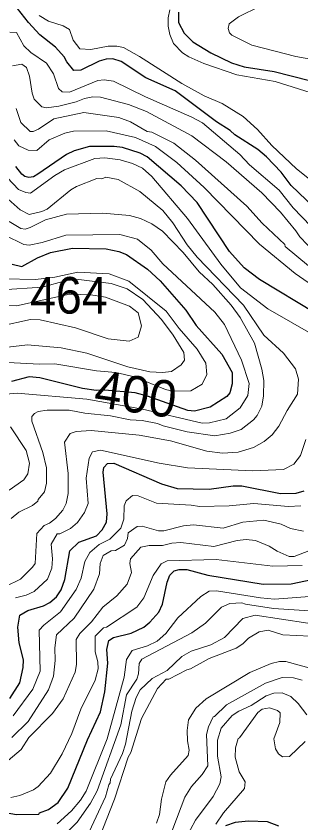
# Model space of a CAD drawing. Extents: x 673.3 to 698.5, y 6984.3 to 7012.3.
# Drawn here: x 677.867 to 678.489, y 6988.991 to 6990.755 of the extents above; entities that cross this region are included whole.
import ezdxf
from ezdxf.enums import TextEntityAlignment as Align

# ---------------------------------------------------------------- set-up
doc = ezdxf.new("R2010")
doc.units = 0
doc.header["$LTSCALE"] = 0.032
doc.layers.add('1', color=7, linetype='Continuous', lineweight=25)
doc.layers.add('2', color=7, linetype='Continuous', lineweight=13)
doc.layers.add('21', color=7, linetype='Continuous')
doc.layers.add('61', color=7, linetype='Continuous')

msp = doc.modelspace()

# ---------------------------------------------------------------- linework, layer by layer
at = {"layer": '1'}
for points in [[(678.5348, 6990.3208), (678.4679, 6990.3843), (678.446, 6990.4136), (678.4146, 6990.4474), (678.3951, 6990.4629), (678.3454, 6990.4954), (678.335, 6990.505), (678.3047, 6990.524), (678.2145, 6990.5913), (678.1504, 6990.6201), (678.0964, 6990.6557), (678.0785, 6990.6614), (678.0638, 6990.6606), (678.0483, 6990.6563), (678.0083, 6990.6365), (677.9931, 6990.6355), (677.9779, 6990.6545), (677.9723, 6990.6658), (677.9533, 6990.6872), (677.9191, 6990.7141), (677.8939, 6990.741), (677.8698, 6990.7716)], [(678.2222, 6990.7631), (678.2219, 6990.7407), (678.2341, 6990.7177), (678.2533, 6990.6987), (678.2923, 6990.6748), (678.3378, 6990.6523), (678.3656, 6990.6438), (678.431, 6990.6336), (678.5082, 6990.6142), (678.5381, 6990.6043), (678.5847, 6990.5818), (678.6337, 6990.5467), (678.7058, 6990.4795), (678.7374, 6990.4595), (678.7677, 6990.4588), (678.7872, 6990.4689), (678.8191, 6990.5), (678.8523, 6990.564), (678.8788, 6990.5944)], [(678.5218, 6990.1049), (678.3988, 6990.1789), (678.3654, 6990.2043), (678.3336, 6990.2401), (678.2629, 6990.3476), (678.2281, 6990.384), (678.1537, 6990.447), (678.1382, 6990.4553), (678.0994, 6990.4673), (678.0815, 6990.4699), (678.0273, 6990.4695), (677.9941, 6990.4603), (677.9768, 6990.4526), (677.9146, 6990.4094), (677.9046, 6990.4033), (677.8944, 6990.4018), (677.886, 6990.4044), (677.8791, 6990.409), (677.8662, 6990.4258)], [(677.8584, 6990.2128), (677.8797, 6990.2071), (677.9138, 6990.2264), (677.9419, 6990.2377), (677.9902, 6990.2477), (678.0641, 6990.246), (678.0912, 6990.2401), (678.1085, 6990.2334), (678.154, 6990.2014), (678.1821, 6990.1758), (678.2379, 6990.112), (678.2607, 6990.0785), (678.3163, 6990.0156), (678.3392, 6989.9759), (678.339, 6989.9506), (678.3342, 6989.9312), (678.3275, 6989.9235), (678.2908, 6989.9002), (678.257, 6989.8911), (678.2421, 6989.8929), (678.154, 6989.9243), (678.1275, 6989.9311), (678.0611, 6989.9374), (678.042, 6989.9367), (678.0124, 6989.9405), (677.9186, 6989.9644), (677.8956, 6989.9659), (677.8567, 6989.9561)], [(678.0548, 6989.632), (678.0648, 6989.6487), (678.0663, 6989.6665), (678.0573, 6989.7579), (678.0585, 6989.7677), (678.0664, 6989.7768), (678.0804, 6989.7777), (678.1847, 6989.7321), (678.2189, 6989.7224), (678.2889, 6989.7209), (678.3411, 6989.728), (678.3606, 6989.7281), (678.4447, 6989.7111), (678.4789, 6989.7118), (678.4964, 6989.7173)], [(677.853, 6989.2634), (677.8748, 6989.2971), (677.8822, 6989.3307), (677.883, 6989.3473), (677.8733, 6989.3847), (677.8709, 6989.4193), (677.8749, 6989.4452), (677.8926, 6989.4552), (677.9266, 6989.4657), (677.9406, 6989.4731), (677.9549, 6989.4857), (677.9653, 6989.501), (677.9735, 6989.5232), (677.9846, 6989.5856), (678.0037, 6989.605), (678.0429, 6989.6185), (678.0548, 6989.632)], [(677.7921, 6989.0228), (677.8681, 6989.0099), (677.9165, 6989.0105), (677.9184, 6989.0132), (677.9378, 6989.0202), (677.959, 6989.0361), (677.9801, 6989.0671), (678.0232, 6989.173), (678.0515, 6989.2343), (678.0606, 6989.2779), (678.0671, 6989.3402), (678.0656, 6989.3701), (678.0695, 6989.3898), (678.0799, 6989.3967), (678.1183, 6989.4059), (678.1463, 6989.4192), (678.1596, 6989.4297), (678.1791, 6989.4515), (678.1869, 6989.4695), (678.1969, 6989.5171), (678.2033, 6989.5325), (678.2127, 6989.5422), (678.2235, 6989.5449), (678.24, 6989.5449), (678.2861, 6989.5325), (678.4069, 6989.5132), (678.4681, 6989.514), (678.5137, 6989.523)], [(678.4412, 6988.9837), (678.4168, 6988.9935), (678.3746, 6988.9953), (678.3459, 6988.992), (678.3247, 6988.9847)]]:
    msp.add_lwpolyline(points, dxfattribs=at)
at = {"layer": '2'}
for points in [[(677.0774, 6990.8085), (677.118, 6990.7392), (677.1463, 6990.7225), (677.2022, 6990.698), (677.231, 6990.6757), (677.2435, 6990.6615), (677.256, 6990.6234), (677.2821, 6990.52), (677.2887, 6990.51), (677.3022, 6990.499), (677.384, 6990.4638), (677.5055, 6990.4177), (677.5778, 6990.3813), (677.5937, 6990.3661), (677.6099, 6990.3358), (677.6245, 6990.2827), (677.631, 6990.277), (677.6589, 6990.2211), (677.6967, 6990.2059), (677.7199, 6990.2013), (677.7579, 6990.1996), (677.8402, 6990.1808), (677.9096, 6990.1788)], [(678.4007, 6990.7768), (678.3532, 6990.7531), (678.3328, 6990.7382), (678.3303, 6990.7276), (678.3332, 6990.7183), (678.3384, 6990.7129), (678.382, 6990.6913), (678.4785, 6990.6668), (678.5313, 6990.6573)], [(678.5234, 6990.5833), (678.4331, 6990.6119), (678.3492, 6990.6263), (678.2775, 6990.6508), (678.2444, 6990.6656), (678.2309, 6990.6746), (678.2108, 6990.6952), (678.2028, 6990.7147), (678.1991, 6990.7329), (678.199, 6990.7509), (678.2031, 6990.7687)], [(677.9173, 6990.7559), (677.9381, 6990.7438), (677.9697, 6990.7337), (677.9838, 6990.7258), (677.9914, 6990.7022), (678.0062, 6990.6835), (678.0303, 6990.6816), (678.0681, 6990.6892), (678.0869, 6990.6891), (678.1016, 6990.6859), (678.1366, 6990.6666), (678.2293, 6990.6073), (678.2778, 6990.5805), (678.3174, 6990.5639), (678.3633, 6990.5353), (678.3947, 6990.5072), (678.4259, 6990.4721), (678.4802, 6990.4209), (678.508, 6990.398), (678.572, 6990.3302), (678.6114, 6990.2776), (678.6725, 6990.2221), (678.7436, 6990.1797)], [(678.5692, 6990.2348), (678.4723, 6990.3359), (678.4422, 6990.3742), (678.3774, 6990.4293), (678.3557, 6990.4526), (678.2746, 6990.5215), (678.2514, 6990.5342), (678.1497, 6990.5786), (678.0799, 6990.6126), (678.0596, 6990.6157), (678.0458, 6990.6143), (677.9835, 6990.5885), (677.9677, 6990.5891), (677.9596, 6990.5965), (677.949, 6990.6288), (677.9335, 6990.6516), (677.8993, 6990.6754), (677.8841, 6990.6897), (677.8681, 6990.7192), (677.8532, 6990.7193)], [(677.859, 6990.6459), (677.8796, 6990.65), (677.8897, 6990.6421), (677.8961, 6990.6237), (677.902, 6990.5865), (677.9065, 6990.5732), (677.9232, 6990.5563), (677.9335, 6990.5539), (677.9603, 6990.5578), (677.9981, 6990.5676), (678.0164, 6990.575), (678.0343, 6990.5783), (678.0514, 6990.5774), (678.1125, 6990.5613), (678.1521, 6990.5464), (678.2514, 6990.4927), (678.3259, 6990.436), (678.4043, 6990.3682), (678.4447, 6990.326), (678.4785, 6990.2857), (678.4868, 6990.2725), (678.5207, 6990.2371)], [(678.5873, 6990.142), (678.455, 6990.251), (678.4545, 6990.2552), (678.405, 6990.3022), (678.3711, 6990.3394), (678.2589, 6990.4395), (678.2116, 6990.4768), (678.1639, 6990.5007), (678.1535, 6990.5026), (678.1167, 6990.5237), (678.0913, 6990.5328), (678.015, 6990.5441), (677.9492, 6990.5299), (677.9159, 6990.5076), (677.9043, 6990.5026), (677.8977, 6990.5027), (677.8771, 6990.5225), (677.8669, 6990.5526)], [(677.863, 6990.4842), (677.8731, 6990.471), (677.8933, 6990.4618), (677.9121, 6990.461), (677.9393, 6990.4843), (677.9736, 6990.4989), (677.9922, 6990.5034), (678.0641, 6990.5042), (678.128, 6990.4893), (678.1716, 6990.4699), (678.2185, 6990.435), (678.2783, 6990.3802), (678.3993, 6990.2559), (678.4768, 6990.1924), (678.5148, 6990.1656)], [(678.5262, 6990.0521), (678.4173, 6990.1149), (678.3573, 6990.1611), (678.3144, 6990.2122), (678.2415, 6990.3121), (678.1634, 6990.4038), (678.1434, 6990.4221), (678.1217, 6990.4327), (678.0943, 6990.4405), (678.0612, 6990.4447), (678.0388, 6990.4438), (677.9729, 6990.4189), (677.9515, 6990.4062), (677.8987, 6990.3675), (677.8882, 6990.369), (677.8723, 6990.3758), (677.848, 6990.4016)], [(678.2409, 6990.2546), (678.2098, 6990.3029), (678.1879, 6990.3296), (678.1377, 6990.3716), (678.0897, 6990.3976), (678.0628, 6990.4025), (678.0541, 6990.3992), (678.0431, 6990.3995), (677.9993, 6990.3823), (677.9863, 6990.3748), (677.935, 6990.3331), (677.9232, 6990.3274), (677.8956, 6990.321), (677.8759, 6990.3314), (677.8368, 6990.366)], [(678.1166, 6989.8725), (678.1426, 6989.8705), (678.176, 6989.8642), (678.1882, 6989.8591), (678.2409, 6989.8461), (678.301, 6989.8373), (678.3352, 6989.8428), (678.3589, 6989.8513), (678.3861, 6989.872), (678.394, 6989.8818), (678.4042, 6989.9024), (678.4075, 6989.925), (678.4083, 6989.9583), (678.4041, 6989.9828), (678.3878, 6990.0395), (678.3564, 6990.096), (678.3371, 6990.1228), (678.2968, 6990.1678), (678.2671, 6990.1954), (678.2318, 6990.2377), (678.1866, 6990.2845), (678.1638, 6990.3008), (678.1386, 6990.3121), (678.1149, 6990.3187), (678.0564, 6990.3243), (677.9769, 6990.3217), (677.9313, 6990.3093), (677.898, 6990.2925), (677.8866, 6990.2893), (677.8773, 6990.2906), (677.8515, 6990.3058)], [(678.0212, 6989.9171), (678.1429, 6989.8957), (678.2733, 6989.865), (678.29, 6989.8654), (678.3258, 6989.8746), (678.3566, 6989.8986), (678.3733, 6989.9253), (678.3764, 6989.952), (678.3597, 6990.0028), (678.3224, 6990.081), (678.3011, 6990.1074), (678.1879, 6990.2133), (678.1622, 6990.243), (678.1325, 6990.267), (678.0936, 6990.2777), (677.9759, 6990.2761), (677.9242, 6990.26), (677.8958, 6990.2543), (677.8841, 6990.2553), (677.8423, 6990.2761)], [(677.8439, 6989.5082), (677.8763, 6989.5241), (677.903, 6989.5501), (677.9083, 6989.5582), (677.9125, 6989.6238), (677.9281, 6989.6413), (677.9397, 6989.6466), (677.9527, 6989.6569), (677.9691, 6989.675), (677.9767, 6989.689), (677.9807, 6989.7112), (677.9808, 6989.7548), (677.9727, 6989.8233), (677.9848, 6989.8427), (677.9984, 6989.8471), (678.0308, 6989.8486), (678.1358, 6989.8388), (678.2045, 6989.8265), (678.2835, 6989.8039), (678.3179, 6989.7997), (678.3527, 6989.8015), (678.3857, 6989.8117), (678.4089, 6989.8246), (678.4266, 6989.8393), (678.4416, 6989.8582), (678.4595, 6989.8924), (678.4824, 6989.928), (678.484, 6989.9613), (678.4775, 6989.9838), (678.4516, 6990.0178), (678.4088, 6990.0571), (678.3639, 6990.1228), (678.2626, 6990.2281), (678.2409, 6990.2546)], [(677.9096, 6990.1788), (677.9518, 6990.1842), (678.0017, 6990.1948), (678.0701, 6990.1916), (678.1137, 6990.1755), (678.1949, 6990.11), (678.2234, 6990.0721), (678.2625, 6990.0269), (678.2818, 6989.9964), (678.2837, 6989.9712), (678.2737, 6989.9503), (678.2492, 6989.9357), (678.2095, 6989.9347), (678.1932, 6989.9387), (678.1261, 6989.9659), (678.0849, 6989.9757), (678.0425, 6989.9794), (677.9515, 6989.9944), (677.9182, 6989.9937), (677.8485, 6989.9976)], [(677.8365, 6990.0295), (677.8921, 6990.0359), (677.9654, 6990.0295), (678.0212, 6990.0181), (678.111, 6989.9883), (678.1594, 6989.977), (678.1871, 6989.9757), (678.2065, 6989.978), (678.2278, 6989.9924), (678.2348, 6990.003), (678.2334, 6990.0197), (678.2102, 6990.0574), (678.1849, 6990.0916), (678.1442, 6990.1355), (678.1097, 6990.1588), (678.0749, 6990.1704), (678.0041, 6990.1793), (677.9772, 6990.1768), (677.9242, 6990.1622), (677.8355, 6990.1565)], [(677.8204, 6990.1229), (677.8679, 6990.1215), (677.984, 6990.1467), (678.0302, 6990.1458), (678.0625, 6990.1402), (678.1146, 6990.1205), (678.1341, 6990.1058), (678.1412, 6990.0777), (678.1339, 6990.0533), (678.1143, 6990.0442), (678.0685, 6990.049), (677.9966, 6990.0736), (677.9192, 6990.0912), (677.8986, 6990.0918), (677.8319, 6990.0767)], [(677.8372, 6989.9278), (677.8692, 6989.9302), (678.0212, 6989.9171)], [(677.8559, 6989.6567), (677.8731, 6989.6701), (677.9026, 6989.6848), (677.9146, 6989.6946), (677.9151, 6989.6982), (677.9287, 6989.7148), (677.9336, 6989.7341), (677.9335, 6989.7675), (677.9255, 6989.8012), (677.901, 6989.8696), (677.901, 6989.8793), (677.9072, 6989.8864), (677.9151, 6989.8902), (677.9347, 6989.8934), (677.983, 6989.8934), (678.0169, 6989.8869), (678.0736, 6989.8812), (678.1166, 6989.8725)], [(677.8515, 6989.7183), (677.8837, 6989.7411), (677.8928, 6989.7543), (677.896, 6989.7775), (677.8886, 6989.805), (677.8545, 6989.8568)], [(677.8657, 6989.4828), (677.8889, 6989.489), (677.9062, 6989.4973), (677.9354, 6989.524), (677.9449, 6989.5477), (677.9465, 6989.5685), (677.9433, 6989.6006), (677.957, 6989.6228), (677.9628, 6989.6231), (677.9861, 6989.6348), (678.0009, 6989.6481), (678.0166, 6989.6695), (678.0247, 6989.6894), (678.0199, 6989.745), (678.0265, 6989.7885), (678.0338, 6989.8021), (678.0513, 6989.8057), (678.1793, 6989.7778), (678.2413, 6989.7674), (678.3841, 6989.7607), (678.4518, 6989.764), (678.4743, 6989.7754), (678.4883, 6989.7944), (678.5003, 6989.8291)], [(678.4896, 6989.684), (678.4623, 6989.6826), (678.3864, 6989.6891), (678.3329, 6989.6842), (678.2681, 6989.6826), (678.2495, 6989.6857), (678.174, 6989.6899), (678.1339, 6989.7061), (678.1212, 6989.7069), (678.1077, 6989.6952), (678.103, 6989.6841), (678.1022, 6989.6551), (678.0955, 6989.6352), (678.0717, 6989.6115), (678.0483, 6989.5994), (678.0282, 6989.5825), (678.0169, 6989.5626), (678.0092, 6989.5261)], [(677.9522, 6989.3459), (677.9516, 6989.3735), (677.9555, 6989.4021), (677.994, 6989.4385), (678.0369, 6989.5018), (678.0491, 6989.5353), (678.0507, 6989.5581), (678.0574, 6989.5758), (678.0746, 6989.5861), (678.0842, 6989.5865), (678.104, 6989.5982), (678.1102, 6989.6126), (678.1119, 6989.6252), (678.1317, 6989.639), (678.1426, 6989.6401), (678.1779, 6989.6296), (678.1896, 6989.6296), (678.2326, 6989.6409), (678.2549, 6989.6426), (678.3199, 6989.6353), (678.3629, 6989.6482), (678.4088, 6989.6532), (678.4466, 6989.6442), (678.4668, 6989.6346), (678.4949, 6989.6288)], [(678.5558, 6989.6051), (678.4746, 6989.5735), (678.464, 6989.5737), (678.4374, 6989.5853), (678.42, 6989.5961), (678.3902, 6989.6082), (678.37, 6989.6108), (678.3503, 6989.6084), (678.2994, 6989.5954), (678.2271, 6989.6044), (678.2075, 6989.6028), (678.1866, 6989.5977), (678.1581, 6989.5978), (678.1394, 6989.5942), (678.1167, 6989.5687), (678.1152, 6989.5585), (678.1191, 6989.5386), (678.11, 6989.5131), (678.0872, 6989.4877), (678.0563, 6989.463), (678.0319, 6989.4308), (678.0062, 6989.405), (677.9983, 6989.392), (677.9986, 6989.3372), (677.9962, 6989.3209), (677.97, 6989.2621), (677.9465, 6989.2305), (677.8951, 6989.1782), (677.8782, 6989.1516), (677.8497, 6989.1277)], [(677.8557, 6989.0465), (677.8754, 6989.051), (677.9048, 6989.0634), (677.9153, 6989.0706), (677.9421, 6989.0997), (677.9679, 6989.1421), (677.9885, 6989.1863), (678.0086, 6989.2398), (678.0396, 6989.3031), (678.046, 6989.3279), (678.0459, 6989.3429), (678.0401, 6989.3652), (678.0398, 6989.3997), (678.0578, 6989.4175), (678.0645, 6989.4192), (678.1311, 6989.4631), (678.1462, 6989.4832), (678.1667, 6989.5318), (678.184, 6989.5574), (678.1969, 6989.5637), (678.3039, 6989.5669), (678.4281, 6989.5523), (678.4925, 6989.5539)], [(678.0092, 6989.5261), (677.9983, 6989.5012), (677.9641, 6989.4524), (677.9273, 6989.4237), (677.9175, 6989.4124), (677.9198, 6989.3229), (677.9033, 6989.2833), (677.8606, 6989.2255)], [(678.5376, 6989.4886), (678.4321, 6989.4806), (678.4008, 6989.483), (678.3052, 6989.4984), (678.2892, 6989.4976), (678.271, 6989.4864), (678.2207, 6989.4395), (678.1945, 6989.4052), (678.1755, 6989.3884), (678.154, 6989.3782), (678.1207, 6989.3683), (678.1086, 6989.3484), (678.1032, 6989.3098), (678.0659, 6989.175), (678.0201, 6989.0609), (678.008, 6989.0407), (677.9877, 6989.0176), (677.9569, 6988.9893)], [(677.9496, 6988.9428), (678.0005, 6988.9931), (678.0292, 6989.034), (678.0439, 6989.061), (678.0958, 6989.2059), (678.1086, 6989.271), (678.1306, 6989.305), (678.1346, 6989.3169), (678.1357, 6989.3398), (678.1419, 6989.3493), (678.2514, 6989.4066), (678.2807, 6989.4278), (678.316, 6989.463), (678.334, 6989.4707), (678.3603, 6989.4724), (678.3687, 6989.4691), (678.4297, 6989.4602), (678.5418, 6989.4529)], [(678.5046, 6989.4277), (678.3896, 6989.4455), (678.3628, 6989.4382), (678.3226, 6989.3965), (678.2929, 6989.3801), (678.2493, 6989.3664), (678.2295, 6989.3547), (678.1973, 6989.3243), (678.1643, 6989.3066), (678.1379, 6989.2819), (678.1292, 6989.2656), (678.1197, 6989.2352), (678.1062, 6989.1632), (678.0994, 6989.1428), (678.073, 6989.0867), (678.0728, 6989.0791), (678.0695, 6989.0746), (678.0626, 6989.0483), (678.0166, 6988.9497)], [(678.0312, 6988.9137), (678.0821, 6989.0434), (678.1116, 6989.1346), (678.1176, 6989.145), (678.141, 6989.2193), (678.1758, 6989.2848), (678.1946, 6989.3051), (678.2008, 6989.3056), (678.2398, 6989.3258), (678.2482, 6989.3276), (678.2886, 6989.3502), (678.3478, 6989.3734), (678.3627, 6989.3826), (678.3752, 6989.3952), (678.398, 6989.4089), (678.4177, 6989.4122), (678.4502, 6989.4023), (678.5095, 6989.3992)], [(677.8575, 6989.1779), (677.8932, 6989.2129), (677.9378, 6989.2821), (677.9489, 6989.3122), (677.9522, 6989.3459)], [(678.708, 6989.2105), (678.6225, 6989.2625), (678.5601, 6989.3082), (678.5227, 6989.3255), (678.4564, 6989.3437), (678.4428, 6989.3437), (678.4244, 6989.3398), (678.378, 6989.32), (678.2822, 6989.2623), (678.2595, 6989.2421), (678.2436, 6989.2162), (678.2405, 6989.1935), (678.2414, 6989.1709), (678.2454, 6989.1505), (678.2432, 6989.1383), (678.2045, 6989.0953), (678.1942, 6989.0806), (678.1845, 6989.043), (678.1803, 6989.0098), (678.1737, 6988.9903)], [(678.1836, 6988.9088), (678.2358, 6989.0476), (678.2505, 6989.0709), (678.2735, 6989.0967), (678.2861, 6989.1161), (678.283, 6989.1844), (678.2874, 6989.2014), (678.2974, 6989.2228), (678.3009, 6989.2235), (678.3269, 6989.249), (678.4122, 6989.2968), (678.4482, 6989.3087), (678.4733, 6989.3086), (678.4925, 6989.3029)], [(678.2375, 6988.9564), (678.2594, 6988.9968), (678.2975, 6989.0492), (678.3123, 6989.0763), (678.3154, 6989.0919), (678.3074, 6989.1367), (678.3074, 6989.1717), (678.3153, 6989.1986), (678.3394, 6989.2258), (678.3536, 6989.2353), (678.3809, 6989.2481), (678.4138, 6989.2687), (678.4306, 6989.2746), (678.4488, 6989.2752), (678.4672, 6989.2678), (678.4836, 6989.2521), (678.5028, 6989.2272)], [(678.3036, 6988.9885), (678.3205, 6989.013), (678.3665, 6989.0663), (678.3675, 6989.0808), (678.3547, 6989.103), (678.3457, 6989.135), (678.3465, 6989.1554), (678.3523, 6989.1759), (678.3552, 6989.1768), (678.3952, 6989.2328), (678.4047, 6989.24), (678.4205, 6989.2427), (678.4383, 6989.2372), (678.4443, 6989.2316), (678.4432, 6989.2106), (678.4305, 6989.1749), (678.4339, 6989.1528), (678.4408, 6989.1421), (678.4491, 6989.1354), (678.4649, 6989.1364), (678.499, 6989.1688)]]:
    msp.add_lwpolyline(points, dxfattribs=at)

# ---------------------------------------------------------------- texts
at = {"layer": '21', "width": 0.95}
msp.add_text('464', height=0.08, dxfattribs=at).set_placement((677.8975, 6990.1045))
at = {"layer": '61'}
msp.add_text('400', height=0.08, rotation=351.573, dxfattribs=at).set_placement((678.1227, 6989.8885), align=Align.CENTER)

doc.saveas('drawing.dxf')
